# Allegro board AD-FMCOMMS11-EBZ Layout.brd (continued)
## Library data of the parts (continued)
R95 = RES: Tolerance: 1; User Part Number: UPN; alternate symbols: R0402_ALT; part number: RES_SM-27K,E007442,1/16W,1,R0402; tolerance: 1
R113 R114 = RES: Tolerance: 1; User Part Number: UPN; alternate symbols: R0402_ALT; part number: RES_SM-12.1K,E007151,1/16W,1,R0402; tolerance: 1
R117 R119 = RES: Tolerance: 1; User Part Number: UPN; alternate symbols: R0402_ALT; part number: RES_SM-20K,E003791,1/16W,1,R0402; tolerance: 1
R121 = RES: Tolerance: 1; User Part Number: UPN; alternate symbols: R0402_ALT; part number: RES_SM-9.53K,E010032,1/16W,1,R0402; tolerance: 1
R122 = RES: Tolerance: 1; User Part Number: UPN; alternate symbols: R0402_ALT; part number: RES_SM-40.2K,E006353,1/16W,1,R0402; tolerance: 1
R140 = RES: Tolerance: 1; User Part Number: UPN; alternate symbols: R0402_ALT; part number: RES_SM-3.3K,E010034,1/10W,1,R0402; tolerance: 1
T1 T5 = XFMRETC1_A_V2: Tolerance: N/A; User Part Number: UPN; alternate symbols: (); part number: XFMRETC1_A_V2_SM-TC1-1-43A+,E012306,AT224-1; tolerance: N/A
T2 = XFMRETC1: Tolerance: N/A; User Part Number: UPN; alternate symbols: (); part number: XFMRETC1_SM-ETC1-1-13,E004586,ETC1; tolerance: N/A
T3 = XFMRTCMXXXX_V4: Tolerance: N/A; User Part Number: UPN; alternate symbols: (); part number: XFMRTCMXXXX_V4_SM-TCM1-43X+,E018598,TSML150W160H160; tolerance: N/A
T4 T6 = XFMRTCMXXXX_V3: Tolerance: N/A; User Part Number: UPN; alternate symbols: (); part number: XFMRTCMXXXX_V3_SM-TCM1-63AX+,E018203,TSML150W160H160; tolerance: N/A
TP1-TP20 TP22-TP27 TP45-TP47 TP50-TP52 TP56 TP57 = NCTESTPAD: Tolerance: N/A; User Part Number: UPN; alternate symbols: (); part number: NCTESTPAD_SM-TESTPAD,E012884,TPSMC30; tolerance: N/A
U1 = AD9162_V4: User Part Number: UPN; Tolerance: N/A; alternate symbols: (); part number: AD9162_V4_SM-AD9162BBCZ,E029000,BGA165_A; tolerance: N/A
U2 = ADP238X: User Part Number: UPN; Tolerance: N/A; alternate symbols: (); part number: ADP238X_SM-ADP2384ACPZN,E012984,QFN24_4X4_2PAD; tolerance: N/A
U3 = ADP237X: Tolerance: N/A; User Part Number: UPN; alternate symbols: (); part number: ADP237X_SM-ADP2370ACPZ-R7,E016641,QFN8_3X3_PAD2_44X1_7; tolerance: N/A
U5 = ADP5073: User Part Number: UPN; Tolerance: N/A; alternate symbols: (); part number: ADP5073_SM-ADP5073ACPZ,E020650,QFN16_3X3_PAD1_6X1_6; tolerance: N/A
U6 = ADP216X: User Part Number: UPN; Tolerance: N/A; alternate symbols: (); part number: ADP216X_SM-ADP2165ACPZ-1.2,E025524,QFN24_4X4_PAD2_5X2_5; tolerance: N/A
U7 U20 = ADM7154: Tolerance: N/A; User Part Number: UPN; alternate symbols: (); part number: ADM7154_SM-ADM7154ACPZ-2.5,E020759,DFN8_3X3_PAD2_44X1_6_A; tolerance: N/A
U8 = ICM24CXX: Tolerance: N/A; User Part Number: UPN; alternate symbols: (); part number: ICM24CXX_SM-M24C02-RMN6TP,E018349,SO8; tolerance: N/A
U9 = ADP196: Tolerance: N/A; User Part Number: UPN; alternate symbols: (); part number: ADP196_SM-ADP196ACBZ,E020438,WLCSP6; tolerance: N/A
U10 U17 = ADM7170: Tolerance: N/A; User Part Number: UPN; alternate symbols: (); part number: ADM7170_SM-ADM7170ACPZ-5.0,E021706,DFN8_3X3_PAD2_38X1_64; tolerance: N/A
U12 = ADM7150: Tolerance: N/A; User Part Number: UPN; alternate symbols: (); part number: ADM7150_SM-ADM7150ACPZ-5.0-R7,E018417,DFN8_3X3_PAD2_38X1_64; tolerance: N/A
U13 = ICFXL4TD245: Tolerance: N/A; User Part Number: UPN; alternate symbols: (); part number: ICFXL4TD245_SM-FXL4TD245BQX,E014936,DQFN16_3_5X2_5_PAD2_15X1_15; tolerance: N/A
U14 = ICFXL2TD245: User Part Number: UPN; Tolerance: N/A; alternate symbols: (); part number: ICFXL2TD245_SM-FXL2TD245L10X,E017923,QFN10_2_1X1_6; tolerance: N/A
U15 = ADM7170: Tolerance: N/A; User Part Number: UPN; alternate symbols: (); part number: ADM7170_SM-ADM7170ACPZ-3.3,E022590,DFN8_3X3_PAD2_38X1_64; tolerance: N/A
U16 = ADL5240: Tolerance: N/A; User Part Number: UPN; alternate symbols: (); part number: ADL5240_SM-ADL5240ACPZ,E015841,QFN32_5X5_PAD3_3X3_3; tolerance: N/A
U18 = ADF4355: Tolerance: N/A; User Part Number: UPN; alternate symbols: (); part number: ADF4355_SM-ADF4355BCPZ,E022645,QFN32_5X5_PAD3_6X3_6; tolerance: N/A
U19 = HMC361: Tolerance: N/A; User Part Number: UPN; alternate symbols: (); part number: HMC361_SM-HMC361S8GE,E022606,S8G; tolerance: N/A
U21 = ADP7182_V6: User Part Number: UPN; Tolerance: N/A; alternate symbols: (); part number: ADP7182_V6_SM-ADP7182ACPZN-1.2,E022662,DFN6_2X2_PAD1_6X1; tolerance: N/A
U22 = ADM1184: Tolerance: N/A; User Part Number: UPN; alternate symbols: (); part number: ADM1184_SM-ADM1184ARMZ,E020084,RM10; tolerance: N/A
U23 U24 = ICFXL4T245: Tolerance: N/A; User Part Number: UPN; alternate symbols: (); part number: ICFXL4T245_SM-FXL4T245BQX,E021654,DQFN14_3X2_5_PAD1_65X1_15; tolerance: N/A
U25 = ADHMC1119: Tolerance: N/A; User Part Number: UPN; alternate symbols: (); part number: ADHMC1119_SM-HMC1119LP4ME,E022877,LP4; tolerance: N/A
U26 = AD7291: User Part Number: UPN; Tolerance: N/A; alternate symbols: (); part number: AD7291_SM-AD7291BCPZ,E017361,QFN20_4X4_PAD2_6X2_6; tolerance: N/A
U27 = ADP1740: Tolerance: N/A; User Part Number: UPN; alternate symbols: (); part number: ADP1740_SM-ADP1740ACPZ-1.2-R7,E011085,QFN16_4X4_PAD2_1X2_1; tolerance: N/A
U28 = ADP176X: User Part Number: UPN; Tolerance: N/A; alternate symbols: (); part number: ADP176X_SM-ADP1761ACPZ,E024608,QFN16_3X3_PAD1_6X1_6; tolerance: N/A
U101 = AD9625: User Part Number: UPN; Tolerance: N/A; alternate symbols: (); part number: AD9625_SM-AD9625BBPZ-2.5,E015711,BGA196H67; tolerance: N/A
VR1-VR3 = ADP1741: Tolerance: N/A; User Part Number: UPN; alternate symbols: (); part number: ADP1741_SM-ADP1741ACPZ,E014231,QFN16_4X4_PAD2_1X2_1; tolerance: N/A
Y1 = XTALOSC6P_V10: User Part Number: UPN; Tolerance: 5; alternate symbols: (); part number: XTALOSC6P_V10_SM-122.88MEGHZ,E019195,YSML276W197H63; tolerance: 5

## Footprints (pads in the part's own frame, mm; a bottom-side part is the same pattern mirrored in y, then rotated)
3PINJUMPER_0402
  rect 0.813x0.889 smd: 1(0,1.27)
  rect 0.889x0.889 smd: 2(0,0)
  rect 0.889x0.813 smd: 3(-1.27,0)
AT224-1
  rect 0.762x1.651 smd: 1(-1.27,1.587) 2(0,1.587) 3(1.27,1.587) 4(1.27,-1.587) 6(-1.27,-1.587)
BGA165_A
  round 0.254 smd: A1(-3.5,-3.5) A2(-3.5,-3) A3(-3.5,-2.5) A4(-3.5,-2) A5(-3.5,-1.5) A6(-3.5,-1) A7(-3.5,-0.5) A8(-3.5,0) A9(-3.5,0.5) A10(-3.5,1) A11(-3.5,1.5) A12(-3.5,2) A13(-3.5,2.5) A14(-3.5,3) A15(-3.5,3.5) B1(-3,-3.5) B2(-3,-3) B3(-3,-2.5) B4(-3,-2) B5(-3,-1.5) B6(-3,-1) B7(-3,-0.5) B8(-3,0) B9(-3,0.5) B10(-3,1) B11(-3,1.5) B12(-3,2) B13(-3,2.5) B14(-3,3) B15(-3,3.5) C1(-2.5,-3.5) C2(-2.5,-3) C4(-2.5,-2) C5(-2.5,-1.5) C6(-2.5,-1) C7(-2.5,-0.5) C8(-2.5,0) C9(-2.5,0.5) C10(-2.5,1) C11(-2.5,1.5) C12(-2.5,2) C14(-2.5,3) C15(-2.5,3.5) D1(-2,-3.5) D2(-2,-3) D3(-2,-2.5) D13(-2,2.5) D14(-2,3) D15(-2,3.5) E1(-1.5,-3.5) E2(-1.5,-3) E3(-1.5,-2.5) E13(-1.5,2.5) E14(-1.5,3) E15(-1.5,3.5) F1(-1,-3.5) F2(-1,-3) F3(-1,-2.5) F6(-1,-1) F7(-1,-0.5) F8(-1,0) F9(-1,0.5) F10(-1,1) F13(-1,2.5) F14(-1,3) F15(-1,3.5) G1(-0.5,-3.5) G2(-0.5,-3) G3(-0.5,-2.5) G6(-0.5,-1) G7(-0.5,-0.5) G8(-0.5,0) G9(-0.5,0.5) G10(-0.5,1) G13(-0.5,2.5) G14(-0.5,3) G15(-0.5,3.5) H1(0,-3.5) H2(0,-3) H3(0,-2.5) H6(0,-1) H7(0,-0.5) H8(0,0) H9(0,0.5) H10(0,1) H13(0,2.5) H14(0,3) H15(0,3.5) J1(0.5,-3.5) J2(0.5,-3) J3(0.5,-2.5) J6(0.5,-1) J7(0.5,-0.5) J8(0.5,0) J9(0.5,0.5) J10(0.5,1) J13(0.5,2.5) J14(0.5,3) J15(0.5,3.5) K1(1,-3.5) K2(1,-3) K3(1,-2.5) K6(1,-1) K7(1,-0.5) K8(1,0) K9(1,0.5) K10(1,1) K13(1,2.5) K14(1,3) K15(1,3.5) L1(1.5,-3.5) L2(1.5,-3) L3(1.5,-2.5) L13(1.5,2.5) L14(1.5,3) L15(1.5,3.5) M1(2,-3.5) M2(2,-3) M3(2,-2.5) M13(2,2.5) M14(2,3) M15(2,3.5) N1(2.5,-3.5) N2(2.5,-3) N4(2.5,-2) N5(2.5,-1.5) N6(2.5,-1) N7(2.5,-0.5) N8(2.5,0) N9(2.5,0.5) N10(2.5,1) N11(2.5,1.5) N12(2.5,2) N14(2.5,3) N15(2.5,3.5) P1(3,-3.5) P2(3,-3) P3(3,-2.5) P4(3,-2) P5(3,-1.5) P6(3,-1) P7(3,-0.5) P8(3,0) P9(3,0.5) P10(3,1) P11(3,1.5) P12(3,2) P13(3,2.5) P14(3,3) P15(3,3.5) R1(3.5,-3.5) R2(3.5,-3) R3(3.5,-2.5) R4(3.5,-2) R5(3.5,-1.5) R6(3.5,-1) R7(3.5,-0.5) R8(3.5,0) R9(3.5,0.5) R10(3.5,1) R11(3.5,1.5) R12(3.5,2) R13(3.5,2.5) R14(3.5,3) R15(3.5,3.5)
BGA196H67
  round 0.356 smd: A1(-5.2,-5.2) A2(-5.2,-4.4) A3(-5.2,-3.6) A4(-5.2,-2.8) A5(-5.2,-2) A6(-5.2,-1.2) A7(-5.2,-0.4) A8(-5.2,0.4) A9(-5.2,1.2) A10(-5.2,2) A11(-5.2,2.8) A12(-5.2,3.6) A13(-5.2,4.4) A14(-5.2,5.2) B1(-4.4,-5.2) B2(-4.4,-4.4) B3(-4.4,-3.6) B4(-4.4,-2.8) B5(-4.4,-2) B6(-4.4,-1.2) B7(-4.4,-0.4) B8(-4.4,0.4) B9(-4.4,1.2) B10(-4.4,2) B11(-4.4,2.8) B12(-4.4,3.6) B13(-4.4,4.4) B14(-4.4,5.2) C1(-3.6,-5.2) C2(-3.6,-4.4) C3(-3.6,-3.6) C4(-3.6,-2.8) C5(-3.6,-2) C6(-3.6,-1.2) C7(-3.6,-0.4) C8(-3.6,0.4) C9(-3.6,1.2) C10(-3.6,2) C11(-3.6,2.8) C12(-3.6,3.6) C13(-3.6,4.4) C14(-3.6,5.2) D1(-2.8,-5.2) D2(-2.8,-4.4) D3(-2.8,-3.6) D4(-2.8,-2.8) D5(-2.8,-2) D6(-2.8,-1.2) D7(-2.8,-0.4) D8(-2.8,0.4) D9(-2.8,1.2) D10(-2.8,2) D11(-2.8,2.8) D12(-2.8,3.6) D13(-2.8,4.4) D14(-2.8,5.2) E1(-2,-5.2) E2(-2,-4.4) E3(-2,-3.6) E4(-2,-2.8) E5(-2,-2) E6(-2,-1.2) E7(-2,-0.4) E8(-2,0.4) E9(-2,1.2) E10(-2,2) E11(-2,2.8) E12(-2,3.6) E13(-2,4.4) E14(-2,5.2) F1(-1.2,-5.2) F2(-1.2,-4.4) F3(-1.2,-3.6) F4(-1.2,-2.8) F5(-1.2,-2) F6(-1.2,-1.2) F7(-1.2,-0.4) F8(-1.2,0.4) F9(-1.2,1.2) F10(-1.2,2) F11(-1.2,2.8) F12(-1.2,3.6) F13(-1.2,4.4) F14(-1.2,5.2) G1(-0.4,-5.2) G2(-0.4,-4.4) G3(-0.4,-3.6) G4(-0.4,-2.8) G5(-0.4,-2) G6(-0.4,-1.2) G7(-0.4,-0.4) G8(-0.4,0.4) G9(-0.4,1.2) G10(-0.4,2) G11(-0.4,2.8) G12(-0.4,3.6) G13(-0.4,4.4) G14(-0.4,5.2) H1(0.4,-5.2) H2(0.4,-4.4) H3(0.4,-3.6) H4(0.4,-2.8) H5(0.4,-2) H6(0.4,-1.2) H7(0.4,-0.4) H8(0.4,0.4) H9(0.4,1.2) H10(0.4,2) H11(0.4,2.8) H12(0.4,3.6) H13(0.4,4.4) H14(0.4,5.2) J1(1.2,-5.2) J2(1.2,-4.4) J3(1.2,-3.6) J4(1.2,-2.8) J5(1.2,-2) J6(1.2,-1.2) J7(1.2,-0.4) J8(1.2,0.4) J9(1.2,1.2) J10(1.2,2) J11(1.2,2.8) J12(1.2,3.6) J13(1.2,4.4) J14(1.2,5.2) K1(2,-5.2) K2(2,-4.4) K3(2,-3.6) K4(2,-2.8) K5(2,-2) K6(2,-1.2) K7(2,-0.4) K8(2,0.4) K9(2,1.2) K10(2,2) K11(2,2.8) K12(2,3.6) K13(2,4.4) K14(2,5.2) L1(2.8,-5.2) L2(2.8,-4.4) L3(2.8,-3.6) L4(2.8,-2.8) L5(2.8,-2) L6(2.8,-1.2) L7(2.8,-0.4) L8(2.8,0.4) L9(2.8,1.2) L10(2.8,2) L11(2.8,2.8) L12(2.8,3.6) L13(2.8,4.4) L14(2.8,5.2) M1(3.6,-5.2) M2(3.6,-4.4) M3(3.6,-3.6) M4(3.6,-2.8) M5(3.6,-2) M6(3.6,-1.2) M7(3.6,-0.4) M8(3.6,0.4) M9(3.6,1.2) M10(3.6,2) M11(3.6,2.8) M12(3.6,3.6) M13(3.6,4.4) M14(3.6,5.2) N1(4.4,-5.2) N2(4.4,-4.4) N3(4.4,-3.6) N4(4.4,-2.8) N5(4.4,-2) N6(4.4,-1.2) N7(4.4,-0.4) N8(4.4,0.4) N9(4.4,1.2) N10(4.4,2) N11(4.4,2.8) N12(4.4,3.6) N13(4.4,4.4) N14(4.4,5.2) P1(5.2,-5.2) P2(5.2,-4.4) P3(5.2,-3.6) P4(5.2,-2.8) P5(5.2,-2) P6(5.2,-1.2) P7(5.2,-0.4) P8(5.2,0.4) P9(5.2,1.2) P10(5.2,2) P11(5.2,2.8) P12(5.2,3.6) P13(5.2,4.4) P14(5.2,5.2)
C0201
  rect 0.305x0.406 smd: 1(-0.318,0) 2(0.318,0)
C0402
  rect 0.61x0.61 smd: 1(-0.495,0) 2(0.495,0)
C0402#2
  rect 0.889x0.813 smd: 1(-0.635,0) 2(0.635,0)
C0603
  rect 1.092x1.194 smd: 1(-0.851,0) 2(0.851,0)
C0603#2
  rect 0.762x0.889 smd: 1(-0.699,0) 2(0.699,0)
C0603H62
  rect 1.092x1.194 smd: 1(-0.851,0) 2(0.851,0)
C0805H53
  rect 1.295x1.6 smd: 1(-0.953,0) 2(0.953,0)
C0805H60
  rect 1.295x1.6 smd: 1(-0.953,0) 2(0.953,0)
C1206H71
  rect 1.6x2.007 smd: 1(-1.397,0) 2(1.397,0)
CNJOHNSON142-0711-201
  round 1.727 smd: 1(0,0)
  custom 0.591x0.591 smd: 2(-2.807,0) 3(2.807,0)
CNSAMTECASP-134488-01
  round 2.54 hole 1.27 unplated: (-2.426,5.715) (51.956,8.763)
  round 0.635 smd: A1(0,0) A2(1.27,0) A3(2.54,0) A4(3.81,0) A5(5.08,0) A6(6.35,0) A7(7.62,0) A8(8.89,0) A9(10.16,0) A10(11.43,0) A11(12.7,0) A12(13.97,0) A13(15.24,0) A14(16.51,0) A15(17.78,0) A16(19.05,0) A17(20.32,0) A18(21.59,0) A19(22.86,0) A20(24.13,0) A21(25.4,0) A22(26.67,0) A23(27.94,0) A24(29.21,0) A25(30.48,0) A26(31.75,0) A27(33.02,0) A28(34.29,0) A29(35.56,0) A30(36.83,0) A31(38.1,0) A32(39.37,0) A33(40.64,0) A34(41.91,0) A35(43.18,0) A36(44.45,0) A37(45.72,0) A38(46.99,0) A39(48.26,0) A40(49.53,0) B1(0,1.27) B2(1.27,1.27) B3(2.54,1.27) B4(3.81,1.27) B5(5.08,1.27) B6(6.35,1.27) B7(7.62,1.27) B8(8.89,1.27) B9(10.16,1.27) B10(11.43,1.27) B11(12.7,1.27) B12(13.97,1.27) B13(15.24,1.27) B14(16.51,1.27) B15(17.78,1.27) B16(19.05,1.27) B17(20.32,1.27) B18(21.59,1.27) B19(22.86,1.27) B20(24.13,1.27) B21(25.4,1.27) B22(26.67,1.27) B23(27.94,1.27) B24(29.21,1.27) B25(30.48,1.27) B26(31.75,1.27) B27(33.02,1.27) B28(34.29,1.27) B29(35.56,1.27) B30(36.83,1.27) B31(38.1,1.27) B32(39.37,1.27) B33(40.64,1.27) B34(41.91,1.27) B35(43.18,1.27) B36(44.45,1.27) B37(45.72,1.27) B38(46.99,1.27) B39(48.26,1.27) B40(49.53,1.27) C1(0,2.54) C2(1.27,2.54) C3(2.54,2.54) C4(3.81,2.54) C5(5.08,2.54) C6(6.35,2.54) C7(7.62,2.54) C8(8.89,2.54) C9(10.16,2.54) C10(11.43,2.54) C11(12.7,2.54) C12(13.97,2.54) C13(15.24,2.54) C14(16.51,2.54) C15(17.78,2.54) C16(19.05,2.54) C17(20.32,2.54) C18(21.59,2.54) C19(22.86,2.54) C20(24.13,2.54) C21(25.4,2.54) C22(26.67,2.54) C23(27.94,2.54) C24(29.21,2.54) C25(30.48,2.54) C26(31.75,2.54) C27(33.02,2.54) C28(34.29,2.54) C29(35.56,2.54) C30(36.83,2.54) C31(38.1,2.54) C32(39.37,2.54) C33(40.64,2.54) C34(41.91,2.54) C35(43.18,2.54) C36(44.45,2.54) C37(45.72,2.54) C38(46.99,2.54) C39(48.26,2.54) C40(49.53,2.54) D1(0,3.81) D2(1.27,3.81) D3(2.54,3.81) D4(3.81,3.81) D5(5.08,3.81) D6(6.35,3.81) D7(7.62,3.81) D8(8.89,3.81) D9(10.16,3.81) D10(11.43,3.81) D11(12.7,3.81) D12(13.97,3.81) D13(15.24,3.81) D14(16.51,3.81) D15(17.78,3.81) D16(19.05,3.81) D17(20.32,3.81) D18(21.59,3.81) D19(22.86,3.81) D20(24.13,3.81) D21(25.4,3.81) D22(26.67,3.81) D23(27.94,3.81) D24(29.21,3.81) D25(30.48,3.81) D26(31.75,3.81) D27(33.02,3.81) D28(34.29,3.81) D29(35.56,3.81) D30(36.83,3.81) D31(38.1,3.81) D32(39.37,3.81) D33(40.64,3.81) D34(41.91,3.81) D35(43.18,3.81) D36(44.45,3.81) D37(45.72,3.81) D38(46.99,3.81) D39(48.26,3.81) D40(49.53,3.81) E1(0,5.08) E2(1.27,5.08) E3(2.54,5.08) E4(3.81,5.08) E5(5.08,5.08) E6(6.35,5.08) E7(7.62,5.08) E8(8.89,5.08) E9(10.16,5.08) E10(11.43,5.08) E11(12.7,5.08) E12(13.97,5.08) E13(15.24,5.08) E14(16.51,5.08) E15(17.78,5.08) E16(19.05,5.08) E17(20.32,5.08) E18(21.59,5.08) E19(22.86,5.08) E20(24.13,5.08) E21(25.4,5.08) E22(26.67,5.08) E23(27.94,5.08) E24(29.21,5.08) E25(30.48,5.08) E26(31.75,5.08) E27(33.02,5.08) E28(34.29,5.08) E29(35.56,5.08) E30(36.83,5.08) E31(38.1,5.08) E32(39.37,5.08) E33(40.64,5.08) E34(41.91,5.08) E35(43.18,5.08) E36(44.45,5.08) E37(45.72,5.08) E38(46.99,5.08) E39(48.26,5.08) E40(49.53,5.08) F1(0,6.35) F2(1.27,6.35) F3(2.54,6.35) F4(3.81,6.35) F5(5.08,6.35) F6(6.35,6.35) F7(7.62,6.35) F8(8.89,6.35) F9(10.16,6.35) F10(11.43,6.35) F11(12.7,6.35) F12(13.97,6.35) F13(15.24,6.35) F14(16.51,6.35) F15(17.78,6.35) F16(19.05,6.35) F17(20.32,6.35) F18(21.59,6.35) F19(22.86,6.35) F20(24.13,6.35) F21(25.4,6.35) F22(26.67,6.35) F23(27.94,6.35) F24(29.21,6.35) F25(30.48,6.35) F26(31.75,6.35) F27(33.02,6.35) F28(34.29,6.35) F29(35.56,6.35) F30(36.83,6.35) F31(38.1,6.35) F32(39.37,6.35) F33(40.64,6.35) F34(41.91,6.35) F35(43.18,6.35) F36(44.45,6.35) F37(45.72,6.35) F38(46.99,6.35) F39(48.26,6.35) F40(49.53,6.35) G1(0,7.62) G2(1.27,7.62) G3(2.54,7.62) G4(3.81,7.62) G5(5.08,7.62) G6(6.35,7.62) G7(7.62,7.62) G8(8.89,7.62) G9(10.16,7.62) G10(11.43,7.62) G11(12.7,7.62) G12(13.97,7.62) G13(15.24,7.62) G14(16.51,7.62) G15(17.78,7.62) G16(19.05,7.62) G17(20.32,7.62) G18(21.59,7.62) G19(22.86,7.62) G20(24.13,7.62) G21(25.4,7.62) G22(26.67,7.62) G23(27.94,7.62) G24(29.21,7.62) G25(30.48,7.62) G26(31.75,7.62) G27(33.02,7.62) G28(34.29,7.62) G29(35.56,7.62) G30(36.83,7.62) G31(38.1,7.62) G32(39.37,7.62) G33(40.64,7.62) G34(41.91,7.62) G35(43.18,7.62) G36(44.45,7.62) G37(45.72,7.62) G38(46.99,7.62) G39(48.26,7.62) G40(49.53,7.62) H1(0,8.89) H2(1.27,8.89) H3(2.54,8.89) H4(3.81,8.89) H5(5.08,8.89) H6(6.35,8.89) H7(7.62,8.89) H8(8.89,8.89) H9(10.16,8.89) H10(11.43,8.89) H11(12.7,8.89) H12(13.97,8.89) H13(15.24,8.89) H14(16.51,8.89) H15(17.78,8.89) H16(19.05,8.89) H17(20.32,8.89) H18(21.59,8.89) H19(22.86,8.89) H20(24.13,8.89) H21(25.4,8.89) H22(26.67,8.89) H23(27.94,8.89) H24(29.21,8.89) H25(30.48,8.89) H26(31.75,8.89) H27(33.02,8.89) H28(34.29,8.89) H29(35.56,8.89) H30(36.83,8.89) H31(38.1,8.89) H32(39.37,8.89) H33(40.64,8.89) H34(41.91,8.89) H35(43.18,8.89) H36(44.45,8.89) H37(45.72,8.89) H38(46.99,8.89) H39(48.26,8.89) H40(49.53,8.89) J1(0,10.16) J2(1.27,10.16) J3(2.54,10.16) J4(3.81,10.16) J5(5.08,10.16) J6(6.35,10.16) J7(7.62,10.16) J8(8.89,10.16) J9(10.16,10.16) J10(11.43,10.16) J11(12.7,10.16) J12(13.97,10.16) J13(15.24,10.16) J14(16.51,10.16) J15(17.78,10.16) J16(19.05,10.16) J17(20.32,10.16) J18(21.59,10.16) J19(22.86,10.16) J20(24.13,10.16) J21(25.4,10.16) J22(26.67,10.16) J23(27.94,10.16) J24(29.21,10.16) J25(30.48,10.16) J26(31.75,10.16) J27(33.02,10.16) J28(34.29,10.16) J29(35.56,10.16) J30(36.83,10.16) J31(38.1,10.16) J32(39.37,10.16) J33(40.64,10.16) J34(41.91,10.16) J35(43.18,10.16) J36(44.45,10.16) J37(45.72,10.16) J38(46.99,10.16) J39(48.26,10.16) J40(49.53,10.16) K1(0,11.43) K2(1.27,11.43) K3(2.54,11.43) K4(3.81,11.43) K5(5.08,11.43) K6(6.35,11.43) K7(7.62,11.43) K8(8.89,11.43) K9(10.16,11.43) K10(11.43,11.43) K11(12.7,11.43) K12(13.97,11.43) K13(15.24,11.43) K14(16.51,11.43) K15(17.78,11.43) K16(19.05,11.43) K17(20.32,11.43) K18(21.59,11.43) K19(22.86,11.43) K20(24.13,11.43) K21(25.4,11.43) K22(26.67,11.43) K23(27.94,11.43) K24(29.21,11.43) K25(30.48,11.43) K26(31.75,11.43) K27(33.02,11.43) K28(34.29,11.43) K29(35.56,11.43) K30(36.83,11.43) K31(38.1,11.43) K32(39.37,11.43) K33(40.64,11.43) K34(41.91,11.43) K35(43.18,11.43) K36(44.45,11.43) K37(45.72,11.43) K38(46.99,11.43) K39(48.26,11.43) K40(49.53,11.43)
CNSMAL562W375H166
  rect 1.702x0.635 smd: 1(1.079,0)
  rect 5.08x2.54 smd: 2(-0.178,4.255) 3(-0.178,4.255) 4(-0.178,-4.255) 5(-0.178,-4.255)
DFN6_2X2_PAD1_6X1
  oval 0.305x0.864 smd: 1(-0.65,-1.082) 2(0,-1.082) 3(0.65,-1.082) 4(0.65,1.082) 5(0,1.082) 6(-0.65,1.082)
  rect 1.6x0.991 smd: PAD(0,0)
DFN8_3X3_PAD2_38X1_64
  oval 0.305x0.838 smd: 1(-0.75,-1.45) 2(-0.25,-1.45) 3(0.25,-1.45) 4(0.75,-1.45) 5(0.75,1.45) 6(0.25,1.45) 7(-0.25,1.45) 8(-0.75,1.45)
  rect 2.388x1.651 smd: PAD(0,0)
DFN8_3X3_PAD2_44X1_6_A
  oval 0.305x0.838 smd: 1(-0.75,-1.45) 2(-0.25,-1.45) 3(0.25,-1.45) 4(0.75,-1.45) 5(0.75,1.45) 6(0.25,1.45) 7(-0.25,1.45) 8(-0.75,1.45)
  rect 2.438x1.6 smd: PAD(0,0)
DQFN14_3X2_5_PAD1_65X1_15
  oval 0.914x0.254 smd: 1(-1.557,-0.25) 7(1.557,-0.25) 8(1.557,0.25) 14(-1.557,0.25)
  oval 0.254x0.914 smd: 2(-1,-1.307) 3(-0.5,-1.307) 4(0,-1.307) 5(0.5,-1.307) 6(1,-1.307) 9(1,1.307) 10(0.5,1.307) 11(0,1.307) 12(-0.5,1.307) 13(-1,1.307)
  rect 1.651x1.143 smd: PAD(0,0)
DQFN16_3_5X2_5_PAD2_15X1_15
  oval 0.889x0.229 smd: 1(-1.795,-0.25) 8(1.795,-0.25) 9(1.795,0.25) 16(-1.795,0.25)
  oval 0.229x0.889 smd: 2(-1.25,-1.294) 3(-0.75,-1.294) 4(-0.25,-1.294) 5(0.25,-1.294) 6(0.75,-1.294) 7(1.25,-1.294) 10(1.25,1.294) 11(0.75,1.294) 12(0.25,1.294) 13(-0.25,1.294) 14(-0.75,1.294) 15(-1.25,1.294)
  rect 1.905x0.991 smd: PAD(0,0)
ETC1
  rect 0.762x1.397 smd: 1(-1.27,1.714) 2(0,1.714) 3(1.27,1.714) 4(1.27,-1.714) 5(-1.27,-1.714)
FLSML126W63H37-2
  rect 1.041x1.803 smd: 1(-1.626,0) 3(1.626,0)
  rect 0.61x1.245 smd: 2(0,-0.927) 4(0,0.927)
JPRSLD03
  rect 0.61x0.762 smd: 1(-0.838,0) 2(0,0) 3(0.838,0)
L0201H13
  rect 0.254x0.305 smd: 1(-0.277,0) 2(0.277,0)
L0402-2
  rect 0.381x0.66 smd: 1(-0.419,0) 2(0.419,0)
L0603
  rect 0.889x0.813 smd: 1(-0.737,0) 2(0.737,0)
L0805
  rect 1.143x1.27 smd: 1(-0.953,0) 2(0.953,0)
L0805_A
  rect 1.016x1.778 smd: 1(-0.889,0) 2(0.889,0)
L1008H47
  rect 0.787x2.007 smd: 1(-0.994,0) 2(0.994,0)
L7144
  rect 0.635x1.016 smd: 1(-0.635,0) 2(0.635,0)
LED0402
  rect 0.508x0.61 smd: A(0.454,0) C(-0.454,0)
LED0603-2
  rect 0.787x0.787 smd: A(0.787,0) C(-0.787,0)
LED0603_A
  rect 0.889x0.787 smd: A(0.845,0) C(-0.845,0)
LP4
  rect 0.254x0.66 smd: 1(-1.251,-1.93) 2(-0.751,-1.93) 3(-0.25,-1.93) 4(0.25,-1.93) 5(0.751,-1.93) 6(1.251,-1.93) 13(1.251,1.93) 14(0.751,1.93) 15(0.25,1.93) 16(-0.25,1.93) 17(-0.751,1.93) 18(-1.251,1.93)
  rect 0.66x0.254 smd: 7(1.93,-1.251) 8(1.93,-0.751) 9(1.93,-0.25) 10(1.93,0.25) 11(1.93,0.751) 12(1.93,1.251) 19(-1.93,1.251) 20(-1.93,0.751) 21(-1.93,0.25) 22(-1.93,-0.25) 23(-1.93,-0.751) 24(-1.93,-1.251)
  rect 2.794x2.794 smd: PAD(0,0)
LSMSQ118H47
  rect 0.991x3.2 smd: 1(-0.995,0) 2(0.995,0)
LSMSQ154H47_A
  custom 0.362x0.362 smd: 1(-1.765,0) 2(1.765,0)
LSMSQ157H83
  rect 1.473x3.683 smd: 1(-1.232,0) 2(1.232,0)
LSMSQ189H123
  custom 0.435x0.435 smd: 1(-2.103,0) 2(2.103,0)
Q1212-8P
  rect 0.406x0.991 smd: 1(-0.991,-1.435) 2(-0.33,-1.435) 3(0.33,-1.435) 4(0.991,-1.435)
  rect 0.406x0.762 smd: 5(0.991,1.549) 6(0.33,1.549) 7(-0.33,1.549) 8(-0.991,1.549)
QFN8_3X3_PAD2_44X1_7
  oval 0.305x0.914 smd: 1(-0.75,-1.557) 2(-0.25,-1.557) 3(0.25,-1.557) 4(0.75,-1.557) 5(0.75,1.557) 6(0.25,1.557) 7(-0.25,1.557) 8(-0.75,1.557)
  rect 2.438x1.702 smd: PAD(0,0)
QFN10_2_1X1_6
  rect 0.305x0.406 smd: 1(-0.75,-0.6) 2(-0.25,-0.6) 3(0.25,-0.6) 4(0.75,-0.6) 6(0.75,0.6) 7(0.25,0.6) 8(-0.25,0.6) 9(-0.75,0.6)
  rect 0.406x0.305 smd: 5(0.85,0) 10(-0.85,0)
QFN16_3X3_PAD1_6X1_6
  oval 0.305x0.889 smd: 1(-0.75,-1.5) 2(-0.25,-1.5) 3(0.25,-1.5) 4(0.75,-1.5) 9(0.75,1.5) 10(0.25,1.5) 11(-0.25,1.5) 12(-0.75,1.5)
  oval 0.889x0.305 smd: 5(1.5,-0.75) 6(1.5,-0.25) 7(1.5,0.25) 8(1.5,0.75) 13(-1.5,0.75) 14(-1.5,0.25) 15(-1.5,-0.25) 16(-1.5,-0.75)
  rect 1.6x1.6 smd: PAD(0,0)
QFN16_4X4_PAD2_1X2_1
  oval 0.356x1.041 smd: 1(-0.975,-1.9) 2(-0.325,-1.9) 3(0.325,-1.9) 4(0.975,-1.9) 9(0.975,1.9) 10(0.325,1.9) 11(-0.325,1.9) 12(-0.975,1.9)
  oval 1.041x0.356 smd: 5(1.9,-0.975) 6(1.9,-0.325) 7(1.9,0.325) 8(1.9,0.975) 13(-1.9,0.975) 14(-1.9,0.325) 15(-1.9,-0.325) 16(-1.9,-0.975)
  rect 2.108x2.108 smd: PAD(0,0)
QFN20_4X4_PAD2_6X2_6
  oval 0.305x1.041 smd: 1(-1,-2.019) 2(-0.5,-2.019) 3(0,-2.019) 4(0.5,-2.019) 5(1,-2.019) 11(1,2.019) 12(0.5,2.019) 13(0,2.019) 14(-0.5,2.019) 15(-1,2.019)
  oval 1.041x0.305 smd: 6(2.019,-1) 7(2.019,-0.5) 8(2.019,0) 9(2.019,0.5) 10(2.019,1) 16(-2.019,1) 17(-2.019,0.5) 18(-2.019,0) 19(-2.019,-0.5) 20(-2.019,-1)
  rect 2.591x2.591 smd: PAD(0,0)
QFN24_4X4_2PAD
  oval 0.305x0.889 smd: 1(-1.25,-2.05) 2(-0.75,-2.05) 3(-0.25,-2.05) 4(0.25,-2.05) 5(0.75,-2.05) 6(1.25,-2.05) 13(1.25,2.05) 14(0.75,2.05) 15(0.25,2.05) 16(-0.25,2.05) 17(-0.75,2.05) 18(-1.25,2.05)
  oval 0.889x0.305 smd: 7(2.05,-1.25) 8(2.05,-0.75) 9(2.05,-0.25) 10(2.05,0.25) 11(2.05,0.75) 12(2.05,1.25) 19(-2.05,1.25) 20(-2.05,0.75) 21(-2.05,0.25) 22(-2.05,-0.25) 23(-2.05,-0.75) 24(-2.05,-1.25)
  rect 1.397x2.692 smd: PAD1(-0.648,0)
  rect 0.94x2.692 smd: PAD2(0.876,0)
QFN24_4X4_PAD2_5X2_5
  oval 0.305x0.991 smd: 1(-1.25,-2) 2(-0.75,-2) 3(-0.25,-2) 4(0.25,-2) 5(0.75,-2) 6(1.25,-2) 13(1.25,2) 14(0.75,2) 15(0.25,2) 16(-0.25,2) 17(-0.75,2) 18(-1.25,2)
  oval 0.991x0.305 smd: 7(2,-1.25) 8(2,-0.75) 9(2,-0.25) 10(2,0.25) 11(2,0.75) 12(2,1.25) 19(-2,1.25) 20(-2,0.75) 21(-2,0.25) 22(-2,-0.25) 23(-2,-0.75) 24(-2,-1.25)
  rect 2.489x2.489 smd: PAD(0,0)
QFN32_5X5_PAD3_3X3_3
  oval 0.305x0.889 smd: 1(-1.75,-2.45) 2(-1.25,-2.45) 3(-0.75,-2.45) 4(-0.25,-2.45) 5(0.25,-2.45) 6(0.75,-2.45) 7(1.25,-2.45) 8(1.75,-2.45) 17(1.75,2.45) 18(1.25,2.45) 19(0.75,2.45) 20(0.25,2.45) 21(-0.25,2.45) 22(-0.75,2.45) 23(-1.25,2.45) 24(-1.75,2.45)
  oval 0.889x0.305 smd: 9(2.45,-1.75) 10(2.45,-1.25) 11(2.45,-0.75) 12(2.45,-0.25) 13(2.45,0.25) 14(2.45,0.75) 15(2.45,1.25) 16(2.45,1.75) 25(-2.45,1.75) 26(-2.45,1.25) 27(-2.45,0.75) 28(-2.45,0.25) 29(-2.45,-0.25) 30(-2.45,-0.75) 31(-2.45,-1.25) 32(-2.45,-1.75)
  rect 3.302x3.302 smd: PAD(0,0)
QFN32_5X5_PAD3_6X3_6
  oval 0.305x0.889 smd: 1(-1.75,-2.451) 2(-1.25,-2.451) 3(-0.75,-2.451) 4(-0.25,-2.451) 5(0.25,-2.451) 6(0.75,-2.451) 7(1.25,-2.451) 8(1.75,-2.451) 17(1.75,2.451) 18(1.25,2.451) 19(0.75,2.451) 20(0.25,2.451) 21(-0.25,2.451) 22(-0.75,2.451) 23(-1.25,2.451) 24(-1.75,2.451)
  oval 0.889x0.305 smd: 9(2.451,-1.75) 10(2.451,-1.25) 11(2.451,-0.75) 12(2.451,-0.25) 13(2.451,0.25) 14(2.451,0.75) 15(2.451,1.25) 16(2.451,1.75) 25(-2.451,1.75) 26(-2.451,1.25) 27(-2.451,0.75) 28(-2.451,0.25) 29(-2.451,-0.25) 30(-2.451,-0.75) 31(-2.451,-1.25) 32(-2.451,-1.75)
  rect 3.607x3.607 smd: PAD(0,0)
R0201
  rect 0.305x0.406 smd: 1(-0.318,0) 2(0.318,0)
R0402
  rect 0.61x0.61 smd: 1(-0.495,0) 2(0.495,0)
R0603
  rect 1.092x1.194 smd: 1(-0.851,0) 2(0.851,0)
R0603#2
  rect 0.889x0.813 smd: 1(-0.737,0) 2(0.737,0)
RM10
  rect 0.305x1.321 smd: 1(-1,-2.171) 2(-0.5,-2.171) 3(0,-2.171) 4(0.5,-2.171) 5(1,-2.171) 6(1,2.171) 7(0.5,2.171) 8(0,2.171) 9(-0.5,2.171) 10(-1,2.171)
S8G
  rect 0.61x1.397 smd: 1(-1.905,-2.807) 2(-0.635,-2.807) 3(0.635,-2.807) 4(1.905,-2.807) 5(1.905,2.807) 6(0.635,2.807) 7(-0.635,2.807) 8(-1.905,2.807)
  rect 2.997x2.692 smd: PAD(0,0)
SO8
  rect 0.61x2.184 smd: 1(-1.905,-2.54) 2(-0.635,-2.54) 3(0.635,-2.54) 4(1.905,-2.54) 5(1.905,2.54) 6(0.635,2.54) 7(-0.635,2.54) 8(-1.905,2.54)
SOD882
  rect 0.356x0.635 smd: A(0.34,0) C(-0.34,0)
SOT523F
  rect 0.508x0.66 smd: 1(-0.5,-0.57) 2(0.5,-0.57) 3(0,0.57)
TPSMC30
  round 0.762 smd: 1(0,0)
TSML150W160H160
  rect 0.762x1.651 smd: 1(-1.27,1.587) 2(0,1.587) 3(1.27,1.587) 4(1.27,-1.587) 5(0,-1.587) 6(-1.27,-1.587)
unnamed#2
  round 1.016 smd: (0,0)
WLCSP6
  round 0.254 smd: A1(-0.5,-0.25) A2(-0.5,0.25) B1(0,-0.25) B2(0,0.25) C1(0.5,-0.25) C2(0.5,0.25)
YSML276W197H63
  rect 1.956x1.778 smd: 1(-2.54,-1.83) 2(0,-1.83) 3(2.54,-1.83) 4(2.54,1.83) 5(0,1.83) 6(-2.54,1.83)

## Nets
12V_P1: C22.2(N2) C23.2(N2) C27.2(N2) C161.1 C163.1 P1.C35 P1.C37 R26.1 R55.2(N2) R95.2(N2) U2.16 U2.17 U2.18 U2.19 U3.1(VIN) U3.2 U5.12 U5.13
AVDD1P3_ADC: C198.1 C200.1 C229.1 C234.1 C258.1 C262.1 C268.1 C272.1 C275.1 C279.1 C283.1 C287.1 C290.1 C294.1 C297.1 C300.1 C303.1 C305.1 C307.1 E23.2(N2) TP12.1(N1) U101.A4 U101.B5 U101.C6 U101.C14 U101.D7 U101.D12 U101.D13 U101.D14 U101.E7 U101.E12 U101.F7 U101.F12 U101.G7 U101.G12 U101.H7 U101.H12 U101.J7 U101.J12
AVDD2P5_ADC: C253.1 C256.1 C257.1 C259.1 C261.1 C264.1 C267.1 C270.1 C274.1 C278.1 C281.1 C285.1 C289.1 C293.1 C296.1 C299.1 C302.1 C304.1 C306.1 C308.1 C309.1 E30.2(N2) TP17.1(N1) U101.A6 U101.A13 U101.A14 U101.B7 U101.B12 U101.C8 U101.C11 U101.D8 U101.D11 U101.E8 U101.E11 U101.F8 U101.F11 U101.G8 U101.G11 U101.H8 U101.H11 U101.J8 U101.J11
AVDD3P3_4355: C13.1 C36.1 C153.1 C160.1 C314.1 C315.1 C329.1 C330.1 C331.1 C332.1 E18.2(N2) L13.2(N2) L14.2(N2) L15.2(N2) L16.2(N2) TP23.1(N1) U18.5 U18.10 U18.16
DVDD1P3_ADC: C231.1 C236.1 C266.1 C269.1 C273.1 C277.1 C280.1 C284.1 C288.1 C292.1 C295.1 C298.1 C301.1 E25.2(N2) TP13.1(N1) U101.D1 U101.D2 U101.D3 U101.F1 U101.F2 U101.F3 U101.H1 U101.H2 U101.H3 U101.K1 U101.K2
DVDD2P5_ADC: C98.2(N2) C126.2(N2) C199.1 C252.1 C255.1 E14.1 E29.2(N2) TP19.1(N1) U14.10(VCCB) U24.14(VCCB) U101.E4
DVDD3P3_4355: C15.1 C151.1 C158.1 C328.1 E16.2(N2) U18.4 U18.26 U18.27
DVDD12_DAC: C78.1 C85.1 C116.1 C119.1 C120.1 C123.1 C124.1 C131.1 C241.1 TP2.1(N1) U1.G6 U1.G7 U1.G9 U1.G10 U1.K6 U1.K7 U1.K8 U1.K9 U1.K10 U27.9 U27.10 U27.11 U27.12 U27.13 U27.14
DVDDIO3P3_ADC: C232.1 C237.1 C282.1 C286.1 C291.1 E26.2(N2) R101.1 U101.F4 U101.F5 U101.G5
GND: C1.2(N2) C3.2(N2) C4.2(N2) C5.2(N2) C6.2(N2) C9.2(N2) C10.2(N2) C13.2(N2) C14.2(N2) C15.2(N2) C16.2(N2) C17.2(N2) C18.2(N2) C20.2(N2) C21.2(N2) C22.1 C23.1 C24.2(N2) C25.2(N2) C26.2(N2) C27.1 C28.2(N2) C30.2(N2) C31.2(N2) C35.2(N2) C36.2(N2) C37.2(N2) C38.1 C42.1 C43.1 C44.1 C45.1 C46.2(N2) C47.2(N2) C48.1 C49.1 C50.1 C51.1 C52.1 C53.1 C54.1 C55.1 C56.1 C57.1 C58.1 C59.1 C60.2(N2) C62.1 C63.2(N2) C64.2(N2) C65.1 C66.1 C67.1 C68.2(N2) C69.1 C70.2(N2) C72.1 C73.2(N2) C74.2(N2) C75.2(N2) C77.2(N2) C78.2(N2) C80.2(N2) C81.2(N2) C82.2(N2) C83.2(N2) C84.2(N2) C85.2(N2) C86.2(N2) C87.2(N2) C88.2(N2) C89.2(N2) C90.1 C91.2(N2) C92.1 C93.2(N2) C94.1 C95.2(N2) C96.2(N2) C97.1 C98.1 C99.2(N2) C100.2(N2) C101.2(N2) C102.2(N2) C103.1 C104.1 C105.2(N2) C106.2(N2) C108.2(N2) C111.2(N2) C115.2(N2) C116.2(N2) C117.1 C118.2(N2) C119.2(N2) C120.2(N2) C121.2(N2) C122.2(N2) C123.2(N2) C124.2(N2) C125.1 C126.1 C128.1 C129.1 C130.2(N2) C131.2(N2) C132.2(N2) C133.2(N2) C134.2(N2) C135.2(N2) C136.2(N2) C137.2(N2) C138.2(N2) C139.2(N2) C140.2(N2) C141.2(N2) C142.2(N2) C143.2(N2) C144.2(N2) C145.2(N2) C146.2(N2) C147.2(N2) C148.2(N2) C150.2(N2) C151.2(N2) C152.2(N2) C153.2(N2) C154.2(N2) C156.1 C157.2(N2) C158.2(N2) C159.2(N2) C160.2(N2) C161.2(N2) C163.2(N2) C164.2(N2) C188.2(N2) C189.2(N2) C194.2(N2) C195.2(N2) C196.2(N2) C197.2(N2) C198.2(N2) C199.2(N2) C200.2(N2) C203.1 C205.2(N2) C206.2(N2) C207.2(N2) C226.2(N2) C227.2(N2) C228.2(N2) C229.2(N2) C230.2(N2) C231.2(N2) C232.2(N2) C233.2(N2) C234.2(N2) C235.2(N2) C236.2(N2) C237.2(N2) C238.2(N2) C241.2(N2) C243.2(N2) C244.2(N2) C245.1 C246.2(N2) C247.2(N2) C248.2(N2) C249.2(N2) C250.2(N2) C251.2(N2) C252.2(N2) C253.2(N2) C254.2(N2) C255.2(N2) C256.2(N2) C257.2(N2) C258.2(N2) C259.2(N2) C260.2(N2) C261.2(N2) C262.2(N2) C263.2(N2) C264.2(N2) C266.2(N2) C267.2(N2) C268.2(N2) C269.2(N2) C270.2(N2) C271.2(N2) C272.2(N2) C273.2(N2) C274.2(N2) C275.2(N2) C276.2(N2) C277.2(N2) C278.2(N2) C279.2(N2) C280.2(N2) C281.2(N2) C282.2(N2) C283.2(N2) C284.2(N2) C285.2(N2) C286.2(N2) C287.2(N2) C288.2(N2) C289.2(N2) C290.2(N2) C291.2(N2) C292.2(N2) C293.2(N2) C294.2(N2) C295.2(N2) C296.2(N2) C297.2(N2) C298.2(N2) C299.2(N2) C300.2(N2) C301.2(N2) C302.2(N2) C303.2(N2) C304.2(N2) C305.2(N2) C306.2(N2) C307.2(N2) C308.2(N2) C309.2(N2) C310.1 C311.2(N2) C312.2(N2) C313.2(N2) C314.2(N2) C315.2(N2) C316.2(N2) C317.2(N2) C320.1 C321.2(N2) C322.2(N2) C326.2(N2) C327.2(N2) C328.2(N2) C329.2(N2) C330.2(N2) C331.2(N2) C332.2(N2) C333.2(N2) C334.1 C335.2(N2) C336.2(N2) C337.2(N2) C338.2(N2) C339.2(N2) C340.2(N2) C341.2(N2) DS1.C FL1.2 FL1.4 J1.2 J1.3(SH2) J2.2 J2.3(SH2) J3.2 J3.3(SH2) J4.2 J4.3 J4.4 J4.5(SH4) J5.2 J5.3(SH2) J6.2 J6.3 J6.4 J6.5(SH4) J7.2 J7.3(SH2) L1.1 P1.A1 P1.A4 P1.A5 P1.A8 P1.A9 P1.A12 P1.A13 P1.A16 P1.A17 P1.A20 P1.A21 P1.A24 P1.A25 P1.A28 P1.A29 P1.A32 P1.A33 P1.A36 P1.A37 P1.A40 P1.B2 P1.B3 P1.B6 P1.B7 P1.B10 P1.B11 P1.B14 P1.B15 P1.B18 P1.B19 P1.B22 P1.B23 P1.B26 P1.B27 P1.B30 P1.B31 P1.B34 P1.B35 P1.B38 P1.B39 P1.C1 P1.C4 P1.C5 P1.C8 P1.C9 P1.C12 P1.C13 P1.C16 P1.C17 P1.C20 P1.C21 P1.C24 P1.C25 P1.C28 P1.C29 P1.C32 P1.C33 P1.C36 P1.C38 P1.C40 P1.D2 P1.D3 P1.D6 P1.D7 P1.D10 P1.D13 P1.D16 P1.D19 P1.D22 P1.D25 P1.D28 P1.D37 P1.D39 P1.E1 P1.E4 P1.E5 P1.E8 P1.E11 P1.E14 P1.E17 P1.E20 P1.E23 P1.E26 P1.E29 P1.E32 P1.E35 P1.E38 P1.E40 P1.F2 P1.F3 P1.F6 P1.F9 P1.F12 P1.F15 P1.F18 P1.F21 P1.F24 P1.F27 P1.F30 P1.F33 P1.F36 P1.F39 P1.G1 P1.G4 P1.G5 P1.G8 P1.G11 P1.G14 P1.G17 P1.G20 P1.G23 P1.G26 P1.G29 P1.G32 P1.G35 P1.G38 P1.G40 P1.H2 P1.H3 P1.H6 P1.H9 P1.H12 P1.H15 P1.H18 P1.H21 P1.H24 P1.H27 P1.H30 P1.H33 P1.H36 P1.H39 P1.J1 P1.J4 P1.J5 P1.J8 P1.J11 P1.J14 P1.J17 P1.J20 P1.J23 P1.J26 P1.J29 P1.J32 P1.J35 P1.J38 P1.J40 P1.K2 P1.K3 P1.K6 P1.K9 P1.K12 P1.K15 P1.K18 P1.K21 P1.K24 P1.K27 P1.K30 P1.K33 P1.K36 P1.K39 Q1.2(S) R2.1 R3.1 R9.1 R12.2(N2) R15.1 R17.1 R22.2(N2) R27.2(N2) R35.1 R37.2(N2) R38.1 R44.2(N2) R46.2(N2) R47.1 R49.2(N2) R51.1 R56.1 R67.1 R71.2(N2) R73.2(N2) R78.2(N2) R79.1 R84.1 R94.2(N2) R96.2(N2) R102.2(N2) R103.1 R104.2(N2) R109.1 R110.1 R113.2(N2) R114.2(N2) R121.2(N2) T2.3 T3.1 T3.2 T4.2 T5.2(NC1) T5.3 T6.2 TP8.1(N1) TP9.1(N1) TP14.1(N1) TP15.1(N1) TP16.1(N1) TP25.1(N1) TP26.1(N1) U1.A13 U1.A14 U1.B1 U1.B2 U1.C2 U1.D2 U1.D3 U1.D13 U1.D14 U1.D15 U1.E1 U1.E2 U1.E3 U1.E13 U1.E14 U1.F6 U1.F7 U1.F8 U1.F9 U1.F10 U1.G2 U1.G3 U1.G8 U1.G13 U1.G14 U1.H1 U1.H3 U1.H6 U1.H7 U1.H8 U1.H9 U1.H10 U1.H13 U1.H15 U1.J6 U1.J7 U1.J8 U1.J9 U1.J10 U1.L1 U1.L2 U1.L14 U1.L15 U1.N6 U1.N7 U1.N10 U1.P1 U1.P15 U1.R2 U1.R5 U1.R8 U1.R11 U1.R14 U2.4 U2.8 U2.9 U2.10 U2.11 U2.12 U2.13 U2.PAD1 U3.8 U3.PAD U5.2 U5.10 U5.PAD U6.7 U6.10 U6.11 U6.12 U6.13 U6.PAD U7.4 U7.PAD U8.3 U8.4 U8.7(WC_N) U9.C2 U10.6 U10.PAD U12.4 U12.PAD U13.2 U13.7 U13.8 U13.9 U14.5 U14.6 U14.7 U15.6 U15.PAD U16.2 U16.3 U16.5 U16.6 U16.7 U16.8 U16.9 U16.11 U16.12 U16.13 U16.14 U16.16 U16.17 U16.18 U16.19 U16.20 U16.22 U16.23 U16.32 U16.PAD U17.6 U17.PAD U18.8 U18.9 U18.13 U18.18 U18.21 U18.31 U18.PAD U19.8 U19.PAD U20.4 U20.PAD U21.5 U22.1 U23.7 U23.8 U23.9 U24.7 U24.8 U24.9 U25.1 U25.4 U25.6 U25.7 U25.8 U25.9 U25.10 U25.11 U25.12 U25.13 U25.15 U25.19 U25.20 U25.21 U25.22 U25.23 U25.24 U25.PAD U26.6 U26.9 U26.PAD U27.6 U27.PAD U28.7 U28.PAD U101.A1 U101.A2 U101.A3 U101.A5 U101.A8 U101.A11 U101.B1 U101.B2 U101.B3 U101.B4 U101.B6 U101.B8 U101.B9 U101.B10 U101.B11 U101.B13 U101.B14 U101.C1 U101.C2 U101.C3 U101.C4 U101.C5 U101.C7 U101.C9 U101.C10 U101.C12 U101.C13 U101.D5 U101.D6 U101.D9 U101.D10 U101.E1 U101.E2 U101.E3 U101.E6 U101.E9 U101.E10 U101.E13 U101.E14 U101.F6 U101.F9 U101.F10 U101.F13 U101.G1 U101.G2 U101.G3 U101.G6 U101.G9 U101.G10 U101.G13 U101.H6 U101.H9 U101.H10 U101.H13 U101.H14 U101.J1 U101.J2 U101.J3 U101.J9 U101.J10 U101.J13 U101.K5 U101.K6 U101.K7 U101.K8 U101.K9 U101.K10 U101.K11 U101.K12 U101.K13 U101.L1 U101.L5 U101.L6 U101.L7 U101.L8 U101.L13 U101.L14 U101.M1 U101.M2 U101.M3 U101.M4 U101.M5 U101.M6 U101.M7 U101.M8 U101.M9 U101.M10 U101.M14 U101.P12 VR1.6 VR1.PAD VR2.6 VR2.PAD VR3.6 VR3.PAD Y1.3
SVDD12_DAC: C106.1 C108.1 C111.1 C115.1 C118.1 C121.1 C122.1 C130.1 C132.1 C133.1 C134.1 C136.1 C311.1 C335.1 E9.2(N2) R45.1 U1.J2 U1.J14 U1.K2 U1.K14 U1.M2 U1.M3 U1.M13(VTT_1P2_2) U1.M14 U1.N2 U1.N14 U1.P3 U1.P4 U1.P6 U1.P7 U1.P9 U1.P10 U1.P12 U1.P13 U1.R1 U1.R15
SVDD12_EN: R53.2(N2) R89.1 U9.C1 U21.3 U22.8
SVDD12PHY_DAC: C313.1 C340.1 E6.2(N2) U1.L3 U1.L13
VDD5_361: C157.1 C164.1 C333.1 E22.2(N2) TP22.1(N1) U19.4(VCC)
VDD_1119: C233.1 C238.1 C337.1 C338.1 E27.2(N2) R137.1 U25.2(VDD)
VDDA12_DAC: C84.1 C93.1 C135.1 E7.2(N2) TP1.1(N1) U1.B13 U1.B14
VDDA25_DAC: C1.1 C3.1 C79.1 C87.1 C96.1 C109.1 C112.1 C113.1 C114.1 C185.1 E1.2(N2) E2.1 E12.2(N2) R41.1 R42.2(N2) R48.1 T1.1 T1.2(NC1) TP4.1(N1) U1.A2 U1.A5 U1.A6 U1.A9 U1.A10 U1.B3 U1.B6 U1.B7 U1.B8 U1.B9 U1.B12 U1.C4 U1.C7 U1.C8 U1.C11 U1.C15
VDDA25_EN: R54.2(N2) U7.7 U22.7
VDDC12_DAC: C107.1 C110.1 C137.1 C138.1 C183.1 C184.1 C341.1 TP3.1(N1) U1.E15 U1.F1 U1.F2 U1.F3 U1.F13 U1.F14 U1.F15 U28.9 U28.10 U28.11 U28.12 U28.13
VIN_N: R63.2(N2) U101.A10
VIN_P: R62.2(N2) U101.A9
3P3V_P1: C56.2(N2) C57.2(N2) E3.1 P1.C39 P1.D36 P1.D38 P1.D40 R28.1 R30.2(N2) R32.1 R40.2(N2) U6.18 U6.19 U6.20 U6.21
3P3VAUX_P1: C83.1 C129.2(N2) C154.1 P1.D32 R34.2(N2) R64.2(N2) U8.8 U26.10 U26.16 U26.17
+INTERNAL_CLK: JP1.1 R33.2(N2) R73.1 Y1.4
-INTERNAL_CLK: JP2.1 R10.2(N2) R12.1 Y1.5
ADC_CLK_N: C201.2(N2) R70.2(N2) U101.G14
ADC_CLK_P: C202.2(N2) R69.1 U101.F14
ARST: R104.1 U101.L9
BST_2165: C61.2(N2) U6.9
BST_2384: C39.2(N2) U2.15
CSB1119: TP50.1(N1) U23.13 U25.16
CSB1119_FMC: P1.G15 U23.2
CSB4355: TP51.1(N1) U18.3 U23.12
CSB4355_FMC: P1.G16 U23.3
CSB5240: TP57.1(N1) U16.29 U23.11
CSB5240_FMC: P1.C10 U23.4
CSB9162: TP52.1(N1) U1.G15 U24.11
CSB9162_FMC: P1.G12 U24.4
CSB9625: TP56.1(N1) U23.10 U101.G4
CSB9625_FMC: P1.C11 U23.5
DAC_CLK_N: C190.2(N2) U1.D1
DAC_CLK_P: C191.2(N2) U1.C1
DAC_OUT_N: E1.1 R41.2(N2) T1.6 U1.A7
DAC_OUT_P: E2.2(N2) R42.1 T1.4 U1.A8
DIVCLK_N: C240.1 U101.P13
DIVCLK_P: C239.1 U101.P14
DOUTA_N: C223.1 U101.P10
DOUTA_P: C222.1 U101.N10
DOUTB_N: C209.1 U101.P9
DOUTB_P: C208.1 U101.N9
DOUTC_N: C211.1 U101.P8
DOUTC_P: C210.1 U101.N8
DOUTD_N: C213.1 U101.P7
DOUTD_P: C212.1 U101.N7
DOUTE_N: C219.1 U101.P5
DOUTE_P: C218.1 U101.N5
DOUTF_N: C215.1 U101.P4
DOUTF_P: C214.1 U101.N4
DOUTG_N: C221.1 U101.P3
DOUTG_P: C220.1 U101.N3
DOUTH_N: C217.1 U101.P2
DOUTH_P: C216.1 U101.N2
DRST: R103.2(N2) U101.M13
DRVDD1P3_ADC: C230.1 C235.1 C271.1 C276.1 E24.2(N2) TP11.1(N1) U101.M11 U101.N1 U101.N6 U101.N11 U101.P1 U101.P6 U101.P11
DRVDD2P5_ADC: C251.1 C254.1 C260.1 C263.1 E28.2(N2) TP18.1(N1) U101.N13 U101.N14
DSYNC_P1_N: P1.H8 R125.1
DSYNC_P1_P: P1.H7 R123.1
DUT_DSYNC_N: R124.2(N2) R125.2(N2) U101.L3
DUT_DSYNC_P: R123.2(N2) R124.1 U101.L4
FB_2384: R15.2(N2) R16.2(N2) U2.2
FPGA_CLK_N: C34.1 T6.4
FPGA_CLK_P: C32.1 T6.6(SEC_DOT)
GA0_P1: P1.C34 U8.2 U26.11
GA1_P1: P1.D35 U8.1 U26.13
IRQ9162: CR5.C U1.G1 U14.8
IRQ9162_FMC: P1.H16 U14.3
IRQ9625: R79.2(N2) U13.11 U101.H5
IRQ9625_FMC: P1.D15 U13.6
MUX_OUT: R11.2(N2) TP20.1(N1) U13.14 U18.30
MUXOUT_FMC: P1.D14 U13.3
PG_1184: R13.1 R30.1 R31.1 R72.1 R75.1 R76.1 R83.1 R85.1 U2.21 U3.6 U5.3 U6.8 U22.6
PG_C2M_P1: P1.D1 R68.1 R91.1 R95.1 R96.1 U2.20 U5.6 U6.23
PLL_REF_IN_N: C186.2(N2) U18.28
PLL_REF_IN_P: C187.2(N2) U18.29
PWDN: R102.1 U101.K4
RBIAS_EXT: R110.2(N2) U101.J6
REXT: R109.2(N2) U101.M12
RF_VDD_AMP_5: C9.1 C20.1 C21.1 C102.1 E15.2(N2) L7.2(N2) U16.1 U16.24(VDD2) U16.25
RST_B: R101.2(N2) U101.K3
RT_2165: C59.2(N2) U6.2 U6.3 U6.24(VREG)
SCL_P1: P1.C30 U8.6 U26.15
SCLK_2P5: TP45.1(N1) U1.J13 U24.13
SCLK_3P3: TP46.1(N1) U13.13 U16.31 U18.1 U25.17 U101.H4
SCLK_FMC: P1.C14 U13.4 U24.2
SDA_P1: P1.C31 U8.5 U26.14
SDIO_2P5: TP47.1(N1) U1.K13 U14.9
SDIO_3P3: TP27.1(N1) U13.12 U16.30 U18.2 U25.18 U101.J4
SDIO_CTRL_FMC: P1.H13 U13.10 U14.4
SDIO_FMC: P1.C15 U13.5 U14.2
SERDIN0_N: C174.1 U1.K15
SERDIN0_P: C173.1 U1.J15
SERDIN1_N: C166.1 U1.N15
SERDIN1_P: C165.1 U1.M15
SERDIN2_N: C176.1 U1.R12
SERDIN2_P: C175.1 U1.R13
SERDIN3_N: C168.1 U1.R9
SERDIN3_P: C167.1 U1.R10
SERDIN4_N: C172.1 U1.R7
SERDIN4_P: C171.1 U1.R6
SERDIN5_N: C178.1 U1.R4
SERDIN5_P: C177.1 U1.R3
SERDIN6_N: C180.1 U1.N1
SERDIN6_P: C179.1 U1.M1
SERDIN7_N: C170.1 U1.K1
SERDIN7_P: C169.1 U1.J1
SPI25_DAC: C89.1 E14.2(N2) R5.1 R6.2(N2) R43.1 U1.K3
SUPPLY1P2: C65.2(N2) C67.2(N2) C69.2(N2) C72.2(N2) E5.2(N2) E7.1 Q4.5 Q4.6 Q4.7 Q4.8 U6.6 U26.3
SUPPLY1P75: C51.2(N2) C53.2(N2) C54.2(N2) C95.1 C194.1 C205.1 C206.1 L5.2(N2) R18.2(N2) R36.2(N2) R82.2(N2) R118.1 R120.1 U27.1 U27.2 U27.3 U27.4 U27.15 U27.16 U28.1 U28.2 U28.3 U28.4 U28.16 VR1.1 VR1.2 VR1.3 VR1.4 VR1.15 VR1.16 VR2.1 VR2.2 VR2.3 VR2.4 VR2.15 VR2.16
SUPPLY3P3: C18.1 C63.1 C70.1 C100.1 C103.2(N2) C125.2(N2) C243.1 C244.1 E3.2(N2) E16.1 E26.1 E27.1 R10.1 R33.1 R52.1 R53.1 R54.1 R92.1 R126.1 U7.8 U9.A1 U9.B1 U13.16(VCCB) U20.7 U20.8 U22.10 U23.14(VCCB) VR3.1 VR3.2 VR3.3 VR3.4 VR3.15 VR3.16 Y1.6(VDD)
SUPPLY5P5: C43.2(N2) C45.2(N2) C50.2(N2) C99.1 C139.1 C140.1 C142.1 L4.2(N2) R20.2(N2) R50.2(N2) U10.5 U10.7 U10.8 U12.7 U12.8 U15.5 U15.7 U15.8 U17.5 U17.7 U17.8
SUPPLYN2P8: C52.2(N2) C316.1 L6.2(N2) R19.2(N2) R65.1 U21.6 U21.PAD
SVPLL12_DAC: C312.1 C339.1 E8.2(N2) U1.N8 U1.N9
SVSYNC33_DAC: C88.1 E13.2(N2) TP6.1(N1) U1.P2 U1.P14
SW_2165: C61.1 L8.1 R21.1 U6.14 U6.15 U6.16 U6.17
SYNC_2370: R24.2(N2) R26.2(N2) U3.4
SYNC_2384: R23.2(N2) U2.23
SYNC_5073: R25.2(N2) R27.1 U5.4
SYNC_DAC_N: R81.1 U1.N11
SYNC_DAC_P: R80.1 U1.N12
TXEN: U1.H2 U24.10
TXEN_FMC: P1.G13 U24.5
UNNAMED_14_ADP216X_I57_AVIN: C58.2(N2) R28.2(N2) U6.22
UNNAMED_14_ADP216X_I57_COMP: C60.1 R29.1 U6.5
UNNAMED_14_ADP216X_I57_SS: C55.2(N2) U6.4
UNNAMED_14_ADP216X_I57_SYNC: R22.1 U6.1
UNNAMED_14_ADP237X_I39_EN: C73.1 R68.2(N2) U3.3
UNNAMED_14_ADP237X_I39_FB: C29.2(N2) R3.2(N2) R4.1 U3.5
UNNAMED_14_ADP237X_I39_SW: L2.1 U3.7
UNNAMED_14_ADP238X_I1_COMP: C35.1 R14.1 U2.1
UNNAMED_14_ADP238X_I1_RT: R2.2(N2) U2.22
UNNAMED_14_ADP238X_I1_SS: C26.1 U2.24
UNNAMED_14_ADP238X_I1_SW1: C39.1 L3.1 U2.5 U2.6 U2.7 U2.14 U2.PAD2
UNNAMED_14_ADP238X_I1_VREG: C31.1 U2.3(VREG)
UNNAMED_14_ADP5073_I95_COMP: C24.1 R1.2(N2) U5.7
UNNAMED_14_ADP5073_I95_FB: R19.1 R39.2(N2) U5.8
UNNAMED_14_ADP5073_I95_SS: R17.2(N2) U5.5
UNNAMED_14_ADP5073_I95_SW: D2.C L1.2(N2) U5.1
UNNAMED_14_ADP5073_I95_VREF: C46.1 R39.1 U5.9
UNNAMED_14_ADP5073_I95_VREG: C47.1 R13.2(N2) U5.11(VREG)
UNNAMED_14_CAP_I5_N1: C40.1 R16.1 R18.1
UNNAMED_14_CAP_I5_N2: C40.2(N2) C42.2(N2) L3.2(N2) L5.1
UNNAMED_14_CAP_I30_N1: C37.1 R14.2(N2)
UNNAMED_14_CAP_I41_N2: C33.2(N2) C38.2(N2) L2.2(N2) L4.1
UNNAMED_14_CAP_I52_N1: C29.1 C33.1 R4.2(N2) R20.1
UNNAMED_14_CAP_I60_N2: C62.2(N2) E5.1 L8.2(N2)
UNNAMED_14_CAP_I75_N1: C64.1 R29.2(N2)
UNNAMED_14_CAP_I121_N1: C28.1 R1.1
UNNAMED_14_CAP_I152_N2: C48.2(N2) D2.A(P) L6.1
UNNAMED_14_DIOLED_I89_N: DS2.C Q1.3
UNNAMED_14_DIOLED_I89_P: DS2.A(P) R32.2(N2)
UNNAMED_14_RES_I86_N2: Q1.1 R31.2(N2)
UNNAMED_14_RES_I176_N1: R21.2(N2) R23.1 R24.1 R25.1
UNNAMED_15_AD9162V4_I79_ISET: R7.1 U1.A15
UNNAMED_15_AD9162V4_I79_PLLLDOB: C6.1 U1.P8
UNNAMED_15_AD9162V4_I79_RESETN: R5.2(N2) U1.J3
UNNAMED_15_AD9162V4_I79_SYSREF: C44.2(N2) U1.N4
UNNAMED_15_AD9162V4_I79_SYSREF_: C104.2(N2) U1.N5
UNNAMED_15_AD9162V4_I79_VBGNEG: C8.1 U1.C12
UNNAMED_15_AD9162V4_I79_VREF: C10.1 U1.B15
UNNAMED_15_DIOLED_I23_P: CR5.A(P) R6.1
UNNAMED_21_ADL5240_I13_AMPIN: C149.2(N2) U16.15
UNNAMED_21_ADL5240_I13_AMPOUT: C7.2(N2) L7.1 U16.10
UNNAMED_21_ADL5240_I13_DSAIN: C7.1 U16.4
UNNAMED_21_ADL5240_I13_DSAOUT: C19.1 U16.21
UNNAMED_21_CAP_I99_N2: C19.2(N2) J4.1
UNNAMED_21_CAP_I102_N1: C2.1 T1.3
UNNAMED_21_CAP_I102_N2: C2.2(N2) R71.1 R77.1
UNNAMED_21_CNBNC3P_I104_CNTR: C155.1 J5.1
UNNAMED_21_FLTRBP4P_I97_IN: FL1.1 R77.2(N2) R78.1
UNNAMED_21_FLTRBP4P_I97_OUT: C149.1 C155.2(N2) FL1.3(OUT)
UNNAMED_22_ADM1184_I145_OUT1: R52.2(N2) U22.9
UNNAMED_22_ADM1184_I145_VIN1: R91.2(N2) R92.2(N2) U22.2
UNNAMED_22_ADM1184_I145_VIN2: R43.2(N2) R44.1 U22.3
UNNAMED_22_ADM1184_I145_VIN3: R45.2(N2) R46.1 U22.4
UNNAMED_22_ADM1184_I145_VIN4: R48.2(N2) R49.1 U22.5(VIN4)
UNNAMED_22_ADM7154_I195_BYP: C66.2(N2) U7.3
UNNAMED_22_ADM7154_I195_REF: C74.1 U7.5 U7.6
UNNAMED_22_ADM7154_I195_VOUT: C77.1 E12.1 U7.2
UNNAMED_22_ADM7154_I195_VREG: C68.1 U7.1(VREG)
UNNAMED_22_ADM7170_I342_SENSE: C101.1 E15.1 U10.1 U10.2(VOUT2) U10.3
UNNAMED_22_ADP176X_I393_PG: R85.2(N2) U28.15
UNNAMED_22_ADP176X_I393_REFCAP: C310.2(N2) U28.5
UNNAMED_22_ADP176X_I393_SS: C86.1 U28.14
UNNAMED_22_ADP176X_I393_VADJ: R84.2(N2) U28.8
UNNAMED_22_ADP176X_I393_VREG: C334.2(N2) U28.6(VREG)
UNNAMED_22_ADP196_I267_VOUT1: C80.1 E13.1 U9.A2 U9.B2(VOUT2)
UNNAMED_22_ADP1740_I381_N5: R82.1 R83.2(N2) U27.5
UNNAMED_22_ADP1740_I381_N7: C195.1 U27.7
UNNAMED_22_ADP7182V6_I320_VOUT: C317.1 E21.1 U21.1(VOUT)
UNNAMED_22_CAP_I259_N1: C82.1 C91.1 E4.2(N2) E6.1 E8.1 E9.1 TP7.1(N1)
UNNAMED_22_CAP_I380_N1: C71.1 Q4.4 R89.2(N2)
UNNAMED_22_CAP_I380_N2: C71.2(N2) E4.1 Q4.1 Q4.2 Q4.3(S3)
UNNAMED_23_AD9625_I119_SYSREF: C105.1 U101.K14
UNNAMED_23_AD9625_I119_SYSREF_1: C141.1 U101.J14
UNNAMED_25_ADHMC1119_I179_ATTIN: C323.2(N2) U25.5
UNNAMED_25_ADHMC1119_I179_ATTOU: C324.1 U25.14
UNNAMED_25_ADHMC1119_I179_P: R137.2(N2) U25.3
UNNAMED_25_CAP_I165_N1: C318.1 T5.6
UNNAMED_25_CAP_I165_N2: C318.2(N2) R57.1
UNNAMED_25_CAP_I166_N1: C319.1 T5.4
UNNAMED_25_CAP_I166_N2: C319.2(N2) R58.1
UNNAMED_25_CAP_I167_N2: C320.2(N2) R59.2(N2) R60.1 R61.1
UNNAMED_25_CAP_I186_N2: C324.2(N2) T5.1
UNNAMED_25_CAP_I188_N1: C323.1 J6.1
UNNAMED_25_RES_I158_N1: R57.2(N2) R59.1 R62.1
UNNAMED_25_RES_I159_N2: R58.2(N2) R60.2(N2) R63.1
UNNAMED_26_ADM7154_I174_BYP: C245.2(N2) U20.3
UNNAMED_26_ADM7154_I174_REF: C248.1 U20.5 U20.6
UNNAMED_26_ADM7154_I174_VOUT: C250.1 E28.1 E29.1 U20.2
UNNAMED_26_ADM7154_I174_VREG: C247.1 U20.1(VREG)
UNNAMED_26_ADP1741_I5_ADJ: R114.1 R119.1 VR2.9
UNNAMED_26_ADP1741_I5_PG: R75.2(N2) R120.2(N2) VR2.5
UNNAMED_26_ADP1741_I5_SS: C226.1 VR2.7
UNNAMED_26_ADP1741_I5_VOUT: C228.1 E23.1 R119.2(N2) VR2.10 VR2.11 VR2.12 VR2.13 VR2.14(VOUT4)
UNNAMED_26_ADP1741_I121_ADJ: R113.1 R117.1 VR1.9
UNNAMED_26_ADP1741_I121_PG: R72.2(N2) R118.2(N2) VR1.5
UNNAMED_26_ADP1741_I121_SS: C207.1 VR1.7
UNNAMED_26_ADP1741_I121_VOUT: C227.1 E24.1 E25.1 R117.2(N2) VR1.10 VR1.11 VR1.12 VR1.13 VR1.14(VOUT4)
UNNAMED_26_ADP1741_I139_ADJ: R121.1 R122.1 VR3.9
UNNAMED_26_ADP1741_I139_PG: R76.2(N2) R126.2(N2) VR3.5
UNNAMED_26_ADP1741_I139_SS: C246.1 VR3.7
UNNAMED_26_ADP1741_I139_VOUT: C249.1 E30.1 R122.2(N2) VR3.10 VR3.11 VR3.12 VR3.13 VR3.14(VOUT4)
UNNAMED_27_CAP_I362_N2: C208.2(N2) P1.A2
UNNAMED_27_CAP_I363_N2: C209.2(N2) P1.A3
UNNAMED_27_CAP_I364_N2: C211.2(N2) P1.A7
UNNAMED_27_CAP_I365_N2: C210.2(N2) P1.A6
UNNAMED_27_CAP_I366_N2: C213.2(N2) P1.A11
UNNAMED_27_CAP_I367_N2: C212.2(N2) P1.A10
UNNAMED_27_CAP_I368_N2: C214.2(N2) P1.A14
UNNAMED_27_CAP_I369_N2: C215.2(N2) P1.A15
UNNAMED_27_CAP_I370_N2: C216.2(N2) P1.A18
UNNAMED_27_CAP_I371_N2: C217.2(N2) P1.A19
UNNAMED_27_CAP_I373_N2: C219.2(N2) P1.B13
UNNAMED_27_CAP_I374_N2: C218.2(N2) P1.B12
UNNAMED_27_CAP_I375_N2: C220.2(N2) P1.B16
UNNAMED_27_CAP_I376_N2: C221.2(N2) P1.B17
UNNAMED_27_CAP_I377_N2: C223.2(N2) P1.C7
UNNAMED_27_CAP_I378_N2: C222.2(N2) P1.C6
UNNAMED_27_CAP_I461_N2: C165.2(N2) P1.A22
UNNAMED_27_CAP_I462_N2: C166.2(N2) P1.A23
UNNAMED_27_CAP_I463_N2: C167.2(N2) P1.A30
UNNAMED_27_CAP_I464_N2: C168.2(N2) P1.A31
UNNAMED_27_CAP_I465_N2: C179.2(N2) P1.B36
UNNAMED_27_CAP_I466_N2: C180.2(N2) P1.B37
UNNAMED_27_CAP_I467_N2: C169.2(N2) P1.A38
UNNAMED_27_CAP_I468_N2: C170.2(N2) P1.A39
UNNAMED_27_CAP_I469_N2: C171.2(N2) P1.B32
UNNAMED_27_CAP_I470_N2: C172.2(N2) P1.B33
UNNAMED_27_CAP_I471_N2: C177.2(N2) P1.A34
UNNAMED_27_CAP_I472_N2: C178.2(N2) P1.A35
UNNAMED_27_CAP_I473_N2: C176.2(N2) P1.A27
UNNAMED_27_CAP_I474_N2: C175.2(N2) P1.A26
UNNAMED_27_CAP_I475_N2: C174.2(N2) P1.C3
UNNAMED_27_CAP_I476_N2: C173.2(N2) P1.C2
UNNAMED_27_CAP_I499_N2: C239.2(N2) P1.D4
UNNAMED_27_CAP_I500_N2: C240.2(N2) P1.D5
UNNAMED_27_CAP_I501_N2: C32.2(N2) P1.B20
UNNAMED_27_CAP_I502_N2: C34.2(N2) P1.B21
UNNAMED_27_CN400PAKV2_I437_TDI: P1.D30 P1.D31
UNNAMED_27_CN400PAKV2_I439_LA03: P1.G10 R81.2(N2)
UNNAMED_27_CN400PAKV2_I439_LA_1: P1.G9 R80.2(N2)
UNNAMED_28_ADF4355_I1290_CPOUT: C75.1 C76.1 R140.1 U18.7
UNNAMED_28_ADF4355_I1290_CREG1: C25.1 U18.25
UNNAMED_28_ADF4355_I1290_CREG2: C30.1 U18.32
UNNAMED_28_ADF4355_I1290_RFOU_1: C242.1 L13.1 U18.12
UNNAMED_28_ADF4355_I1290_RFOU_2: C11.1 L16.1 U18.15
UNNAMED_28_ADF4355_I1290_RFOUTA: C265.1 L14.1 U18.11
UNNAMED_28_ADF4355_I1290_RFOUTB: C12.1 L15.1 U18.14
UNNAMED_28_ADF4355_I1290_RSET: R9.2(N2) U18.22
UNNAMED_28_ADF4355_I1290_VBIAS: C14.1 C81.1 U18.24
UNNAMED_28_ADF4355_I1290_VREF: C4.1 C5.1 U18.23
UNNAMED_28_CAP_I1241_N1: C127.1 J2.1 R37.1
UNNAMED_28_CAP_I1241_N2: C127.2(N2) T3.3
UNNAMED_28_CAP_I1252_N1: C204.1 J3.1
UNNAMED_28_CAP_I1252_N2: C204.2(N2) T4.3
UNNAMED_28_CAP_I1268_N1: C202.1 JP3.2(COM)
UNNAMED_28_CAP_I1269_N1: C201.1 JP4.2(COM)
UNNAMED_28_CAP_I1272_N2: C203.2(N2) R69.2(N2) R70.1
UNNAMED_28_CAP_I1301_N1: C188.1 C190.1 JP22.2(COM)
UNNAMED_28_CAP_I1302_N1: C189.1 C191.1 JP5.2(COM)
UNNAMED_28_CAP_I1313_N1: C187.1 JP1.2(COM) R8.1
UNNAMED_28_CAP_I1314_N1: C186.1 JP2.2(COM) R8.2(N2)
UNNAMED_28_CAP_I1349_N2: C76.2(N2) R94.1
UNNAMED_28_CAP_I1359_N2: C12.2(N2) JP22.1
UNNAMED_28_CAP_I1360_N2: C11.2(N2) JP5.1
UNNAMED_28_CAP_I1372_N2: C242.2(N2) U19.5
UNNAMED_28_CAP_I1373_N2: C265.2(N2) U19.7
UNNAMED_28_CAP_I1380_N1: C41.1 J7.1
UNNAMED_28_CAP_I1380_N2: C41.2(N2) T6.3
UNNAMED_28_CNBNC3P_I1213_CNTR: J1.1 T2.1
UNNAMED_28_DIOLED_I1378_P: DS1.A(P) R11.1
UNNAMED_28_HMC361_I1297_OUT: JP3.3 U19.3
UNNAMED_28_HMC361_I1297_OUTN: JP4.3 U19.1
UNNAMED_28_NC3PJMPR_I1233_B: JP5.3 T4.4
UNNAMED_28_NC3PJMPR_I1234_A: JP3.1 T3.6(SEC_DOT)
UNNAMED_28_NC3PJMPR_I1235_A: JP4.1 T3.4
UNNAMED_28_NC3PJMPR_I1280_B: JP22.3 T4.6(SEC_DOT)
UNNAMED_28_NC3PJMPR_I1389_B: JP1.3 T2.5(N4)
UNNAMED_28_NC3PJMPR_I1390_B: JP2.3 T2.4
UNNAMED_29_ADM7150_I83_BYP: C143.1 U12.3
UNNAMED_29_ADM7150_I83_REF: C146.1 U12.5 U12.6
UNNAMED_29_ADM7150_I83_VOUT: C147.1 E17.1 U12.2
UNNAMED_29_ADM7150_I83_VREG: C145.1 U12.1(VREG)
UNNAMED_29_ADM7170_I32_SENSE: C148.1 E18.1 U15.1 U15.2(VOUT2) U15.3
UNNAMED_29_ADM7170_I92_SENSE: C150.1 E22.1 U17.1 U17.2(VOUT2) U17.3
UNNAMED_30_AD7291_I369_DCAP: C128.2(N2) U26.8
UNNAMED_30_AD7291_I369_VIN0: R55.1 R56.2(N2) U26.18
UNNAMED_30_AD7291_I369_VIN1: R40.1 R47.2(N2) U26.19
UNNAMED_30_AD7291_I369_VIN2: R34.1 R35.2(N2) U26.20
UNNAMED_30_AD7291_I369_VIN3: R36.1 R38.2(N2) U26.1
UNNAMED_30_AD7291_I369_VIN4: R50.1 R51.2(N2) U26.2
UNNAMED_30_AD7291_I369_VIN6: R64.1 R65.2(N2) U26.4
UNNAMED_30_AD7291_I369_VIN7: R66.1 R67.2(N2) U26.5
UNNAMED_30_AD7291_I369_VREF: C156.2(N2) U26.7(VREF)
VADJ_P1: C90.2(N2) C92.2(N2) C94.2(N2) C97.2(N2) P1.E39 P1.F40 P1.G39 P1.H40 P1.J39 P1.K40 R66.2(N2) U13.1 U13.15 U14.1 U23.1 U23.6 U24.1 U24.6
VCM: C197.1 R61.2(N2) U101.A7
VM_BYP: C144.1 U101.A12
VMON: TP10.1(N1) U101.E5
VNEG12_DAC: C8.2(N2) C49.2(N2) C79.2(N2) C107.2(N2) C109.2(N2) C110.2(N2) C112.2(N2) C113.2(N2) C114.2(N2) C117.2(N2) C183.2(N2) C184.2(N2) C185.2(N2) C321.1 C322.1 E21.2(N2) R7.2(N2) TP5.1(N1) U1.A1 U1.A3 U1.A4 U1.A11 U1.A12 U1.B4 U1.B5 U1.B10 U1.B11 U1.C5 U1.C6 U1.C9 U1.C10 U1.C14
VP_BYP: C196.1 U101.N12(VP_BYP)
VTUNE_4355: C336.1 R140.2(N2) U18.20
VVCO5_4355: C16.1 C17.1 C152.1 C159.1 C326.1 C327.1 E17.2(N2) TP24.1(N1) U18.6 U18.17(VVCO) U18.19

Pads without a net: P1 B1 B4 B5 B8 B9 B24 B25 B28 B29 B40 C18 C19 C22 C23 C26 C27 D8 D9 D11 D12 D17 D18 D20 D21 D23 D24 D26 D27 D29 D33 D34 E2 E3 E6 E7 E9 E10 E12 E13 E15 E16 E18 E19 E21 E22 E24 E25 E27 E28 E30 E31 E33 E34 E36 E37 F1 F4 F5 F7 F8 F10 F11 F13 F14 F16 F17 F19 F20 F22 F23 F25 F26 F28 F29 F31 F32 F34 F35 F37 F38 G2 G3 G6 G7 G18 G19 G21 G22 G24 G25 G27 G28 G30 G31 G33 G34 G36 G37 H1 H4 H5 H10 H11 H14 H17 H19 H20 H22 H23 H25 H26 H28 H29 H31 H32 H34 H35 H37 H38 J2 J3 J6 J7 J9 J10 J12 J13 J15 J16 J18 J19 J21 J22 J24 J25 J27 J28 J30 J31 J33 J34 J36 J37 K1 K4 K5 K7 K8 K10 K11 K13 K14 K16 K17 K19 K20 K22 K23 K25 K26 K28 K29 K31 K32 K34 K35 K37 K38; T2 2; T3 5; T4 1 5; T6 1 5; U1 H14 P5 P11; U5 14 15 16; U10 4; U13 PAD; U15 4; U16 26 27 28; U17 4; U19 2 6; U21 2 4; U23 PAD; U24 3 12 PAD; U26 12; U27 8; U101 D4 J5 L2 L10 L11 L12; VR1 8; VR2 8; VR3 8; Y1 1 2

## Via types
v1: diameter 0.381, hole 0.203, TOP to BOTTOM, 832 vias
v2: diameter 0.254, hole 0.127, TOP to BOTTOM, 98 vias
v3: diameter 0.508, hole 0.254, TOP to BOTTOM, 916 vias
v4: diameter 0.381, hole 0.203, TOP to L2_GROUND, 406 vias
v5: diameter 0.66, hole 0.406, TOP to BOTTOM, 32 vias
v6: diameter 0.381, hole 0.203, L11_GROUND to BOTTOM, 262 vias

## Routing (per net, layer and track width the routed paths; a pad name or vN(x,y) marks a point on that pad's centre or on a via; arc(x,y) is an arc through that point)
12V_P1: length 31.5
  TOP w0.305: 17.77,65.3 C22.2 ; C22.2 18.92,66.31 ; C22.2 20.08,65.3 ; U3.2 21.09,64.6 ; 21.12,65.1 U3.1 21.94,65.61
  BOTTOM w0.203: R26.1 80.01,27.39
  BOTTOM w0.305: 66.41,9.38 U5.13 65.9,8.74 66.14,8.49 ; 78.8,31.35 U2.18 78,30.84 ; 81.03,27.28 R55.2 81.69,26.62 ; 67.77,9.89 67.53,10.13 U5.12 66.65,9.62 ; U2.17 78.8,31.85 ; 77.7,30.55 U2.19 77.2,29.95 77.72,29.42 ; U2.16 78.74,32.35 78.87,32.22
  BOTTOM w0.406: P1.C37 v3(95.55,14.11)
  BOTTOM w0.508: R95.2 v3(35.29,25.23) ; P1.C35 v3(95.55,16.65)
  BOTTOM w0.762: 68.5,7.07 C27.2 67.5,8.23 ; 79.23,31.9 C23.2 ; C23.2 80.39,30.9 ; C23.2 81.55,31.9 ; C161.1 84.8,26.12 ; C161.1 83.44,27.28 ; C161.1 82.08,26.12 ; 82.08,29.55 C163.1 ; C163.1 83.44,28.39 ; C163.1 84.8,29.55
  vias: v3(17.65,67.27) v3(18.29,67.27) v3(18.92,67.27) v3(19.56,67.27) v3(20.19,67.27) v3(67.44,8.47) v3(68.07,8.47) v3(68.71,8.47) v3(68.71,7.83) v3(69.34,8.47) v3(69.34,7.83) v3(83.82,28.15) v3(83.82,27.52) v3(84.45,28.15) v3(84.45,27.52) v3(85.09,29.55) v3(85.09,28.92) v3(85.09,28.28) v3(85.09,27.65)
